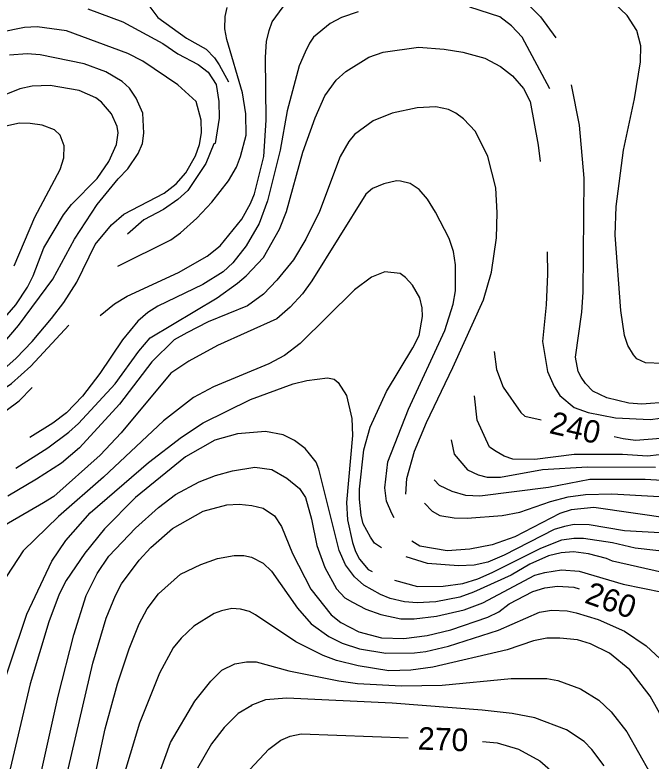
# Model space of a CAD drawing. Extents: x -555860 to -552701, y -1187050 to -1182291.
# Drawn here: x -555524.6 to -555242.8, y -1186105 to -1185774.2 of the extents above; entities that cross this region are included whole.
import ezdxf

# ---------------------------------------------------------------- set-up
doc = ezdxf.new("R2010")
doc.units = 0
for name, color, linetype in [('Level 40', 7, 'Continuous'), ('Level 41', 7, 'Continuous'), ('Level 42', 7, 'Continuous')]:
    doc.layers.add(name, color=color, linetype=linetype)

msp = doc.modelspace()

# ---------------------------------------------------------------- linework, layer by layer
at = {"layer": 'Level 40'}
for points in [[(-555479, -1185885.61), (-555455.55, -1185873.85), (-555451.25, -1185870.8), (-555444.04, -1185864.28), (-555437.38, -1185857.21), (-555430.03, -1185847.78), (-555426.43, -1185841.68), (-555424.62, -1185836.96), (-555422.13, -1185827.53), (-555422.27, -1185818.11), (-555423.79, -1185808.68), (-555430.73, -1185785.11), (-555431.56, -1185780.39), (-555431.43, -1185774.87), (-555430.59, -1185770.96)], [(-555524.87, -1185885.49), (-555515.72, -1185863.86), (-555504.49, -1185842.79), (-555502.97, -1185837.52), (-555502.83, -1185832.25), (-555504.49, -1185827.53), (-555506.99, -1185825.18), (-555512.53, -1185823.1), (-555517.82, -1185822.39), (-555522.52, -1185822.13), (-555537.49, -1185825.46)], [(-555356.58, -1185997.15), (-555357.69, -1185995.29), (-555360.01, -1185989.76), (-555360.7, -1185983.94), (-555359.46, -1185972.29), (-555350.31, -1185949), (-555334.22, -1185914.06), (-555330.48, -1185902.41), (-555329.37, -1185896.59), (-555329.37, -1185884.94), (-555330.34, -1185879.11), (-555332.28, -1185873.29), (-555338.24, -1185861.65), (-555341.85, -1185855.82), (-555345.58, -1185851.6), (-555349.47, -1185848.89), (-555353.75, -1185847.89), (-555355.57, -1185847.78), (-555361.12, -1185849.03), (-555366.13, -1185851.1), (-555369.16, -1185853.74), (-555393.01, -1185892.15), (-555397.17, -1185897.83), (-555402.72, -1185903.8), (-555408.54, -1185908.93), (-555434.88, -1185920.79), (-555447.5, -1185927.72), (-555455.49, -1185932.99), (-555477.45, -1185959.54), (-555486.88, -1185969.38), (-555507.4, -1185987.68), (-555511.98, -1185990.59), (-555532.19, -1186002.18)], [(-555312.25, -1185923.48), (-555311.28, -1185931.35), (-555308.37, -1185939.26), (-555300.53, -1185950.52), (-555298.72, -1185952.05), (-555291.48, -1185953.71)], [(-555585.08, -1186013.99), (-555576.87, -1185995.59), (-555573.54, -1185985.05), (-555567.86, -1185974.51), (-555562.73, -1185967.44), (-555559.26, -1185965.22), (-555544.43, -1185959.54), (-555535, -1185954.27), (-555522.66, -1185945.25), (-555516.9, -1185939.33)], [(-555259.08, -1185961.14), (-555255.19, -1185962.03), (-555249.64, -1185962.73), (-555238.55, -1185961.89)], [(-555505.32, -1186127.03), (-555490.07, -1186061.59), (-555484.11, -1186041.62), (-555480.09, -1186031.64), (-555477.32, -1186026.37), (-555469.55, -1186015.97), (-555464.42, -1186010.28), (-555454.85, -1186001.97), (-555441.13, -1185994.2), (-555430.73, -1185991.43), (-555425.18, -1185991.15), (-555419.63, -1185991.7), (-555414.64, -1185992.95), (-555409.65, -1185996.28), (-555406.46, -1186001), (-555401.61, -1186013.06), (-555393.57, -1186028.86), (-555384.55, -1186040.24), (-555380.26, -1186043.56), (-555372.21, -1186047.72), (-555362.23, -1186050.36), (-555352.25, -1186050.63), (-555341.99, -1186049.39), (-555331.45, -1186046.89), (-555315.09, -1186041.21), (-555310.23, -1186038.85), (-555305.66, -1186035.38), (-555295.12, -1186029.84), (-555289.85, -1186028.17), (-555284.31, -1186027.48), (-555276.96, -1186027.89), (-555274.68, -1186028.7)], [(-555233.28, -1185997.67), (-555268.22, -1185992.54), (-555278.2, -1185993.65), (-555283.2, -1185995.31), (-555303.16, -1186005.57), (-555313.15, -1186009.18), (-555323.13, -1186011.12), (-555333.11, -1186011.81), (-555345.18, -1186009.73), (-555348.74, -1186007.59)], [(-555420.46, -1186108.73), (-555412.15, -1186099.72), (-555406.74, -1186095.7), (-555402.72, -1186094.03), (-555397.73, -1186092.93), (-555350.44, -1186094.73)], [(-555317.54, -1186096.36), (-555310.93, -1186096.95), (-555301.5, -1186099.72), (-555292.07, -1186104.85), (-555283.61, -1186112.34), (-555280.15, -1186117.61), (-555277.79, -1186123.43), (-555275.85, -1186132.86), (-555272.52, -1186161.14), (-555271.27, -1186165.86), (-555266, -1186179.58)]]:
    msp.add_lwpolyline(points, dxfattribs=at)
at = {"layer": 'Level 41'}
for points in [[(-555299, -1185767.77), (-555291.79, -1185775.12), (-555284.96, -1185784.3)], [(-555237.72, -1185928.76), (-555245.34, -1185928.48), (-555249.07, -1185926.73), (-555250.61, -1185924.87), (-555253.03, -1185920.79), (-555254.63, -1185916.28), (-555256.16, -1185905.18), (-555258.65, -1185871.91), (-555258.24, -1185859.15), (-555255.05, -1185834.19), (-555250.15, -1185811.39), (-555247.56, -1185794.96), (-555247.37, -1185787.87), (-555249.05, -1185781.05), (-555253.38, -1185774.5), (-555259.15, -1185768.96)], [(-555492.29, -1185771.52), (-555476.76, -1185777.34), (-555459.01, -1185786.91), (-555452.36, -1185791.49), (-555443.48, -1185796.2), (-555439.05, -1185799.53), (-555435.44, -1185805.07), (-555434.19, -1185812.56), (-555434.05, -1185820.05), (-555435.86, -1185831.14), (-555436.41, -1185831.42), (-555440.02, -1185840.01), (-555447.92, -1185852.08), (-555452.36, -1185856.1), (-555458.73, -1185860.4), (-555467.44, -1185865.1), (-555474.71, -1185871.44)], [(-555486.88, -1185907.5), (-555480.5, -1185902.27), (-555474.82, -1185898.94), (-555452.08, -1185888.41), (-555439.46, -1185881.2), (-555433.64, -1185876.62), (-555424.07, -1185864.7), (-555420.19, -1185857.76), (-555418.52, -1185853.6), (-555414.36, -1185836.96), (-555413.26, -1185820.88), (-555413.53, -1185792.87), (-555413.12, -1185785.94), (-555411.92, -1185781.06), (-555410.62, -1185777.34), (-555405.77, -1185770.69)], [(-555287.71, -1185807.02), (-555299.97, -1185784), (-555304.69, -1185779.01), (-555309.82, -1185775.12), (-555323.13, -1185770.82)], [(-555372.49, -1185772.9), (-555379.98, -1185775.4), (-555384.97, -1185778.03), (-555392.32, -1185784.14), (-555394.12, -1185786.77), (-555396.08, -1185790.71), (-555398.7, -1185796.75), (-555403.97, -1185816.72), (-555407.16, -1185834.19), (-555412.7, -1185856.65), (-555416.45, -1185866.64), (-555422.13, -1185876.62), (-555428.09, -1185884.11), (-555432.39, -1185888.13), (-555441.27, -1185893.68), (-555461.23, -1185903.38), (-555465.67, -1185906.15), (-555470.1, -1185910.03), (-555476.9, -1185918.22), (-555487.02, -1185933.19), (-555494.65, -1185943.18), (-555501.72, -1185950.66), (-555507.82, -1185955.24), (-555518.02, -1185961.52)], [(-555532.22, -1185933.61), (-555524.04, -1185926.4), (-555516.97, -1185919.05), (-555508.37, -1185908.79), (-555502.95, -1185901.73), (-555497.14, -1185892.7), (-555489.07, -1185875.92), (-555481.86, -1185867.32), (-555476.39, -1185862.49), (-555458.46, -1185853.19), (-555453.19, -1185849.03), (-555448.89, -1185844.17), (-555444.59, -1185836.69), (-555442.79, -1185831.7), (-555441.96, -1185826.43), (-555442.1, -1185820.88), (-555444.32, -1185812.56), (-555452.36, -1185805.21), (-555467.89, -1185794.67), (-555474.54, -1185791.34), (-555501.72, -1185781.22), (-555514.75, -1185779.42), (-555520.3, -1185779.84), (-555531.39, -1185782.05)], [(-555524.17, -1185975.14), (-555510.04, -1185966.19), (-555500.75, -1185959.26), (-555496.45, -1185955.38), (-555480.23, -1185937.77), (-555469.69, -1185923.21), (-555464.7, -1185917.38), (-555435.03, -1185899.64), (-555425.96, -1185893.07), (-555422.13, -1185889.93), (-555414.5, -1185881.75), (-555407.43, -1185869.13), (-555404.24, -1185861.37), (-555397.03, -1185835.02), (-555391.62, -1185819.77), (-555387.33, -1185810.06), (-555382.33, -1185803.13), (-555378.04, -1185799.25), (-555367.78, -1185792.87), (-555361.4, -1185790.79), (-555345.87, -1185788.57), (-555334.5, -1185789.41), (-555326.18, -1185790.65), (-555316.47, -1185793.43), (-555309.54, -1185797.03), (-555304.13, -1185801.19), (-555299.28, -1185806.88), (-555296.37, -1185812.56), (-555292.76, -1185831.97), (-555291.95, -1185839.23)], [(-555530.7, -1185920.85), (-555522.93, -1185911.84), (-555507.82, -1185891.32), (-555498.25, -1185873.57), (-555488.13, -1185858.32), (-555478.84, -1185846.95), (-555474.54, -1185842.51), (-555469.97, -1185835.58), (-555468.03, -1185831.14), (-555467.47, -1185826.7), (-555467.89, -1185817.83), (-555470.8, -1185811.17), (-555473.85, -1185806.74), (-555477.04, -1185803.69), (-555484.25, -1185799.39), (-555493.95, -1185795.92), (-555513.37, -1185791.9), (-555519.19, -1185791.48), (-555526.95, -1185792.04)], [(-555235.22, -1185945.95), (-555246.87, -1185946.78), (-555252.69, -1185946.36), (-555262.4, -1185944.01), (-555268.64, -1185941.09), (-555271.8, -1185937.62), (-555273.77, -1185934.86), (-555275.15, -1185932.36), (-555276.26, -1185925.98), (-555273.49, -1185906.01), (-555272.94, -1185897.14), (-555272.43, -1185846.64), (-555274.48, -1185823.14), (-555278.03, -1185805.23)], [(-555533.06, -1185912.81), (-555524.18, -1185902.69), (-555519.05, -1185894.92), (-555516.56, -1185889.93), (-555511.84, -1185877.45), (-555503.11, -1185862.89), (-555499.5, -1185858.32), (-555488.13, -1185846.67), (-555483, -1185839.18), (-555479.53, -1185831.69), (-555478.84, -1185826.43), (-555479.26, -1185823.65), (-555481.75, -1185818.11), (-555486.19, -1185812.84), (-555488.69, -1185811.03), (-555496.17, -1185807.71), (-555508.93, -1185805.49), (-555516.97, -1185805.77), (-555522.38, -1185807.01), (-555532.5, -1185810.9)], [(-555351.36, -1185986.7), (-555351, -1185979.78), (-555347.53, -1185967.58), (-555342.23, -1185954.87), (-555330.58, -1185930.47), (-555317.03, -1185900.47), (-555313.42, -1185888.27), (-555311.34, -1185873.01), (-555310.93, -1185861.92), (-555311.62, -1185850.83), (-555315.09, -1185836.96), (-555320.63, -1185825.87), (-555325.9, -1185820.32), (-555329.23, -1185817.83), (-555332.56, -1185816.17), (-555338.1, -1185814.92), (-555346.42, -1185815.33), (-555357.52, -1185817.83), (-555365.83, -1185821.16), (-555374.16, -1185827.26), (-555376.65, -1185830.31), (-555380.53, -1185836.96), (-555389.68, -1185861.37), (-555395.65, -1185873.57), (-555401.19, -1185882.72), (-555408.54, -1185891.87), (-555414.5, -1185897.97), (-555421.57, -1185903.24), (-555439.05, -1185910.31), (-555448.49, -1185915.1), (-555454.02, -1185918.22), (-555464, -1185928.06), (-555478.29, -1185946.78), (-555496.03, -1185966.19), (-555503.94, -1185972.99), (-555515.03, -1185980.06), (-555527.71, -1185987.63)], [(-555288.84, -1185879.27), (-555288.65, -1185889.16), (-555289.21, -1185902.77), (-555290.82, -1185919.05), (-555288.74, -1185932.36), (-555285.69, -1185939.02), (-555283.2, -1185942.9), (-555276.82, -1185948.31), (-555270.72, -1185950.52), (-555258.52, -1185952.88), (-555243.26, -1185953.57), (-555234.11, -1185952.33)], [(-555362.19, -1186010.52), (-555365.28, -1186008.48), (-555367.08, -1186005.71), (-555370.27, -1185999.89), (-555371.24, -1185996), (-555371.94, -1185988.93), (-555371.94, -1185984.49), (-555369.99, -1185967.03), (-555367.22, -1185957.04), (-555360.01, -1185941.23), (-555348.36, -1185921.82), (-555345.59, -1185916.28), (-555344.07, -1185907.96), (-555344.2, -1185904.07), (-555345.18, -1185899.64), (-555348.5, -1185894.09), (-555351.51, -1185890.59), (-555353.91, -1185888.82), (-555360.7, -1185888.13), (-555366.67, -1185890.49), (-555374.16, -1185896.03), (-555398.28, -1185919.88), (-555405.21, -1185925.15), (-555412.15, -1185928.89), (-555436.55, -1185939.15), (-555445.42, -1185943.87), (-555458.73, -1185954.13), (-555485.36, -1185979.09), (-555505.32, -1185996.56), (-555520.85, -1186011.81), (-555530.7, -1186026.8)], [(-555576.55, -1185957.6), (-555550.8, -1185950.52), (-555542.31, -1185947.27), (-555536.52, -1185944.56), (-555526.12, -1185937.63), (-555517.53, -1185930), (-555500.75, -1185911.7)], [(-555534.12, -1186083.54), (-555519.33, -1186039.96), (-555508.24, -1186016.39), (-555502, -1186007.23), (-555491.18, -1185995.03), (-555465.39, -1185972.71), (-555450.83, -1185961.48), (-555441.13, -1185955.1), (-555420.19, -1185944.7), (-555401.33, -1185937.77), (-555395.23, -1185936.24), (-555386.08, -1185935.13), (-555383.19, -1185935.64), (-555381.42, -1185937.23), (-555377.76, -1185942.9), (-555375.4, -1185953.16), (-555374.99, -1185960.65), (-555377.76, -1185990.32), (-555377.2, -1185998.08), (-555374.99, -1186008.07), (-555373.78, -1186012.12), (-555371.94, -1186015.55), (-555368.05, -1186020.13), (-555366.34, -1186020.98)], [(-555234.11, -1185968.69), (-555244.37, -1185969.8), (-555255.46, -1185969.1), (-555276.82, -1185969.1), (-555294.29, -1185971.32), (-555303.99, -1185971.18), (-555307.88, -1185969.8), (-555311.4, -1185967.82), (-555314.39, -1185965.78), (-555319.8, -1185953.85), (-555321.02, -1185943.06)], [(-555215.53, -1186026.37), (-555259.9, -1186016.39), (-555262.54, -1186015.28), (-555270.56, -1186013.11), (-555277.09, -1186012.23), (-555282.64, -1186012.64), (-555288.19, -1186014.03), (-555296.51, -1186017.77), (-555304.83, -1186022.63), (-555321.46, -1186030.11), (-555327.49, -1186032.42), (-555338.1, -1186034.41), (-555346.42, -1186034.83), (-555351.97, -1186034.41), (-555358.44, -1186032.91), (-555362.65, -1186031.22), (-555370.07, -1186026.97), (-555374.15, -1186023.32), (-555378.18, -1186018.05), (-555380.95, -1186011.67), (-555389.96, -1185975.62), (-555391.21, -1185972.57), (-555394.08, -1185968.81), (-555396.06, -1185966.47), (-555400.77, -1185962.87), (-555405.77, -1185960.37), (-555413.53, -1185958.84), (-555426.01, -1185959.95), (-555436, -1185962.73), (-555449.03, -1185970.07), (-555471.21, -1185988.1), (-555484.94, -1186002.1), (-555493.68, -1186012.78), (-555501.86, -1186024.98), (-555504.91, -1186031.08), (-555509.48, -1186043.29), (-555517.8, -1186070.74), (-555527.79, -1186113.45)], [(-555331.4, -1185962.64), (-555330.02, -1185968.93), (-555324.1, -1185975.9), (-555319.39, -1185978.12), (-555315.36, -1185979.09), (-555309.54, -1185979.09), (-555290.96, -1185975.76), (-555270.99, -1185974.51), (-555240.77, -1185974.65)], [(-555526.82, -1186172.79), (-555505.46, -1186076.29), (-555498.53, -1186049.11), (-555492.98, -1186031.64), (-555488.13, -1186021.93), (-555483, -1186014.17), (-555471.21, -1186001.69), (-555460.95, -1185992.54), (-555453.47, -1185986.85), (-555442.93, -1185981.17), (-555435.72, -1185978.39), (-555428.23, -1185976.31), (-555418.25, -1185974.65), (-555410.76, -1185975.76), (-555404.1, -1185979.64), (-555398.56, -1185984.22), (-555395.92, -1185988.1), (-555393.15, -1185997.81), (-555390.79, -1186009.45), (-555387.33, -1186019.16), (-555382.2, -1186028.59), (-555378.45, -1186032.61), (-555375.02, -1186034.64), (-555369.16, -1186037.6), (-555362.51, -1186040.1), (-555353.63, -1186041.9), (-555347.81, -1186041.9), (-555337.83, -1186040.79), (-555325.62, -1186038.02), (-555317.34, -1186034.89), (-555294.29, -1186022.63), (-555289.85, -1186021.38), (-555282.44, -1186020.29), (-555274.6, -1186020.82), (-555255.19, -1186026.65), (-555237.72, -1186030.11)], [(-555230.23, -1185981.03), (-555245.48, -1185980.2), (-555269.88, -1185980.2), (-555288.19, -1185983.66), (-555318.69, -1185987.54), (-555324.79, -1185987.27), (-555330.89, -1185985.47), (-555336.58, -1185982.83), (-555338.86, -1185980.36)], [(-555343.14, -1185990.61), (-555339.74, -1185994.24), (-555336.3, -1185996.14), (-555330.06, -1185997.25), (-555324.24, -1185997.39), (-555308.71, -1185996.14), (-555300.94, -1185994.62), (-555287.35, -1185989.9), (-555279.59, -1185987.82), (-555271.83, -1185986.85), (-555260.18, -1185986.57), (-555223.3, -1185988.66)], [(-555236.2, -1186003.95), (-555254.63, -1186002.94), (-555270.16, -1186000.3), (-555276.82, -1186000.16), (-555281.2, -1186000.98), (-555285.69, -1186002.38), (-555307.88, -1186013.75), (-555315.12, -1186016.82), (-555321.19, -1186018.19), (-555328.12, -1186018.47), (-555341.85, -1186017.36), (-555351.34, -1186014.49)], [(-555356.38, -1186024.75), (-555346.32, -1186027.64), (-555334.82, -1186027.54), (-555326.18, -1186026.23), (-555319.57, -1186024.25), (-555313.15, -1186021.38), (-555291.65, -1186010.7), (-555282.36, -1186006.96), (-555276.99, -1186006.18), (-555272.66, -1186006.13), (-555259.9, -1186008.07), (-555249.92, -1186010.42), (-555231.61, -1186012.5)], [(-555493.68, -1186132.58), (-555484.66, -1186090.71), (-555479.12, -1186070.74), (-555473.99, -1186055.21), (-555469.55, -1186044.12), (-555465.95, -1186037.46), (-555460.95, -1186030.94), (-555451.25, -1186022.21), (-555442.23, -1186017.91), (-555434.89, -1186015.28), (-555427.4, -1186013.89), (-555423.24, -1186013.85), (-555419.77, -1186014.58), (-555414.64, -1186017.22), (-555410.9, -1186020.82), (-555399.39, -1186037.19), (-555393.43, -1186044.12), (-555385.52, -1186049.8), (-555379.7, -1186052.71), (-555371.94, -1186055.21), (-555360.29, -1186057.15), (-555347.53, -1186057.01), (-555342.54, -1186056.46), (-555332.56, -1186054.1), (-555310.37, -1186047.03), (-555292.21, -1186038.99), (-555286.9, -1186038.11), (-555279.97, -1186038.36), (-555275.98, -1186039.26), (-555266.28, -1186042.18), (-555254.63, -1186047.45), (-555244.93, -1186053.96), (-555230.64, -1186067.27)], [(-555236.82, -1186087.65), (-555243.26, -1186076.28), (-555252.28, -1186064.64), (-555261.15, -1186057.15), (-555269.61, -1186052.99), (-555275.43, -1186051.33), (-555283.2, -1186050.5), (-555289.02, -1186050.5), (-555294.84, -1186051.74), (-555306.49, -1186055.63), (-555339.49, -1186063.39), (-555349.2, -1186064.78), (-555358.9, -1186065.05), (-555372.49, -1186062.84), (-555382.2, -1186060.48), (-555388.02, -1186058.26), (-555400.22, -1186052.16), (-555417.97, -1186040.23), (-555420.74, -1186038.71), (-555424.72, -1186037.61), (-555428.51, -1186037.32), (-555433.14, -1186038.36), (-555436.27, -1186039.54), (-555445.29, -1186045.23), (-555450.97, -1186050.5), (-555454.44, -1186054.79), (-555460.54, -1186066.03), (-555469.41, -1186088.21), (-555477.73, -1186115.67)], [(-555464.42, -1186120.93), (-555455.69, -1186096.81), (-555444.87, -1186078.5), (-555437.8, -1186069.63), (-555432.95, -1186064.78), (-555427.14, -1186061.92), (-555421.99, -1186061.02), (-555417.71, -1186061.09), (-555403.27, -1186065.05), (-555381.09, -1186069.49), (-555372.77, -1186070.6), (-555353.36, -1186071.71), (-555335.33, -1186071.43), (-555304.83, -1186068.38), (-555289.02, -1186068.38), (-555284.03, -1186069.35), (-555274.04, -1186072.96), (-555266, -1186078.09), (-555260.46, -1186083.22), (-555253.52, -1186092.09), (-555243.19, -1186110.31)], [(-555263.64, -1186107.07), (-555269.05, -1186099.86), (-555272.38, -1186096.39), (-555280.28, -1186091.12), (-555294.29, -1186085.85), (-555304.27, -1186083.91), (-555317.58, -1186082.39), (-555357.52, -1186079.34), (-555404.1, -1186077.12), (-555413.53, -1186077.81), (-555420.01, -1186080.32), (-555419.63, -1186080.31), (-555425.73, -1186083.91), (-555431.84, -1186090.15), (-555437.52, -1186097.36), (-555443.76, -1186108.18)]]:
    msp.add_lwpolyline(points, dxfattribs=at)
at = {"layer": 'Level 42'}
msp.add_lwpolyline([(-555409.28, -1185740.02), (-555416.28, -1185742.72), (-555425.18, -1185747.39), (-555435.16, -1185751.69), (-555448.06, -1185755.99), (-555459.29, -1185757.65), (-555460.64, -1185758.54), (-555462.48, -1185760.15), (-555466.07, -1185766.18), (-555466.07, -1185767.88), (-555464.84, -1185770.69), (-555461.23, -1185775.4), (-555448.61, -1185784.55), (-555439.88, -1185789.41), (-555436.13, -1185793.19), (-555434.05, -1185796.34), (-555430.03, -1185803.82)], dxfattribs=at)

# ---------------------------------------------------------------- texts
at = {"layer": 'Level 40'}
for s, rotation, p in [('240', 347.0832, (-555288.32, -1185959.56)), ('260', 340.6043, (-555272.71, -1186034.69)), ('270', 357.8143, (-555346.23, -1186099.89))]:
    msp.add_text(s, height=10, rotation=rotation, dxfattribs=at).set_placement(p)

doc.saveas('drawing.dxf')
